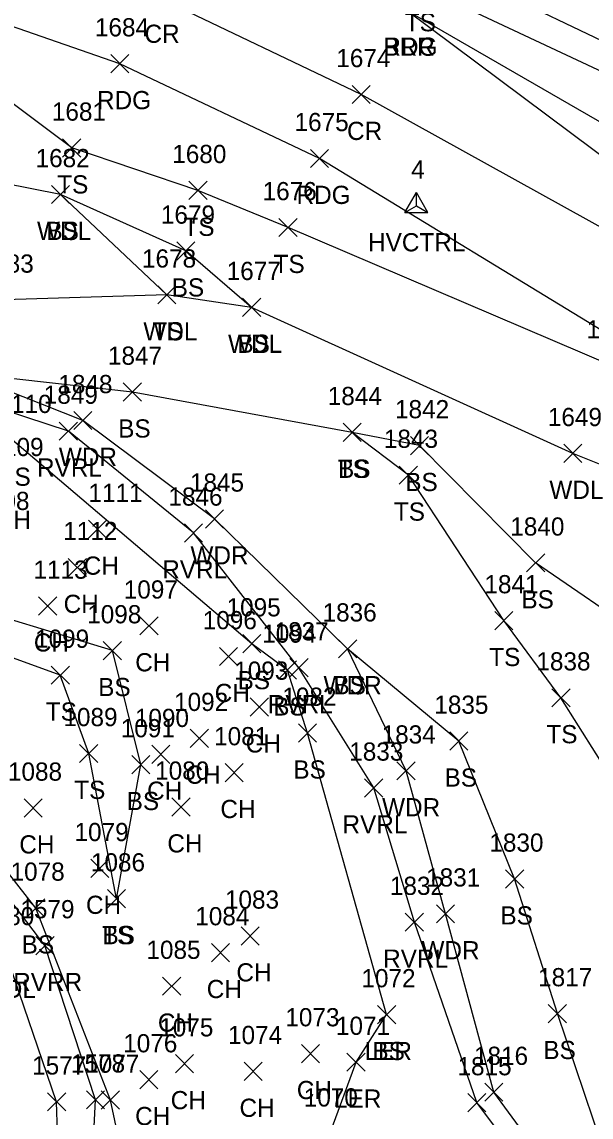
# Model space of a CAD drawing. Extents: x 1600281 to 1602254, y 862855 to 863227.
# Drawn here: x 1602106.5 to 1602169.1, y 862981.5 to 863101.9 of the extents above; entities that cross this region are included whole.
import ezdxf

# ---------------------------------------------------------------- set-up
doc = ezdxf.new("R2010")
doc.units = 0
for name, color, linetype in [('C_A', 7, 'Continuous'), ('C_I', 7, 'Continuous'), ('CPSM', 7, 'Continuous'), ('L_A', 7, 'Continuous'), ('L_I', 7, 'Continuous'), ('L_TIC', 7, 'Continuous'), ('LABL', 7, 'Continuous'), ('LARO', 7, 'Continuous'), ('LAWA', 7, 'Continuous'), ('LAWE', 7, 'Continuous'), ('LELB', 7, 'Continuous'), ('P_A', 7, 'Continuous'), ('P_I', 7, 'Continuous'), ('P_TIC', 7, 'Continuous'), ('PEU', 7, 'Continuous'), ('PRC', 7, 'Continuous')]:
    doc.layers.add(name, color=color, linetype=linetype)

msp = doc.modelspace()

# ---------------------------------------------------------------- linework, layer by layer
at = {"layer": 'CPSM'}
for p, q in [((1602148.62, 863080.92), (1602149.87, 863083.09)), ((1602151.12, 863080.92), (1602149.87, 863083.09)), ((1602149.87, 863081.64), (1602149.87, 863083.09)), ((1602148.62, 863080.92), (1602149.87, 863081.64)), ((1602149.87, 863081.64), (1602149.87, 863081.64)), ((1602149.87, 863081.64), (1602151.12, 863080.92)), ((1602148.62, 863080.92), (1602151.12, 863080.92))]:
    msp.add_line(p, q, dxfattribs=at)
at = {"layer": 'L_TIC'}
for points in [[(1602110.99, 863087), (1602112.99, 863089)], [(1602112.99, 863087), (1602110.99, 863089)], [(1602124.86, 863082.34), (1602126.86, 863084.34)], [(1602126.86, 863082.34), (1602124.86, 863084.34)], [(1602109.76, 863081.89), (1602111.76, 863083.89)], [(1602111.76, 863081.89), (1602109.76, 863083.89)], [(1602109.76, 863081.89), (1602111.76, 863083.89)], [(1602111.76, 863081.89), (1602109.76, 863083.89)], [(1602134.77, 863078.26), (1602136.77, 863080.26)], [(1602136.77, 863078.26), (1602134.77, 863080.26)], [(1602123.54, 863075.68), (1602125.54, 863077.68)], [(1602125.54, 863075.68), (1602123.54, 863077.68)], [(1602121.45, 863070.86), (1602123.45, 863072.86)], [(1602123.45, 863070.86), (1602121.45, 863072.86)], [(1602121.45, 863070.86), (1602123.45, 863072.86)], [(1602123.45, 863070.86), (1602121.45, 863072.86)], [(1602130.76, 863069.49), (1602132.76, 863071.49)], [(1602132.76, 863069.49), (1602130.76, 863071.49)], [(1602130.76, 863069.49), (1602132.76, 863071.49)], [(1602132.76, 863069.49), (1602130.76, 863071.49)], [(1602117.66, 863060.18), (1602119.66, 863062.18)], [(1602119.66, 863060.18), (1602117.66, 863062.18)], [(1602112.21, 863057.06), (1602114.21, 863059.06)], [(1602114.21, 863057.06), (1602112.21, 863059.06)], [(1602110.62, 863055.89), (1602112.62, 863057.89)], [(1602112.62, 863055.89), (1602110.62, 863057.89)], [(1602141.82, 863055.75), (1602143.82, 863057.75)], [(1602143.82, 863055.75), (1602141.82, 863057.75)], [(1602141.82, 863055.75), (1602143.82, 863057.75)], [(1602143.82, 863055.75), (1602141.82, 863057.75)], [(1602149.21, 863054.3), (1602151.21, 863056.3)], [(1602151.21, 863054.3), (1602149.21, 863056.3)], [(1602166.07, 863053.44), (1602168.07, 863055.44)], [(1602168.07, 863053.44), (1602166.07, 863055.44)], [(1602147.99, 863051.05), (1602149.99, 863053.05)], [(1602149.99, 863051.05), (1602147.99, 863053.05)], [(1602126.68, 863046.24), (1602128.68, 863048.24)], [(1602128.68, 863046.24), (1602126.68, 863048.24)], [(1602113.82, 863045.11), (1602115.82, 863047.11)], [(1602115.82, 863045.11), (1602113.82, 863047.11)], [(1602124.37, 863044.7), (1602126.37, 863046.7)], [(1602126.37, 863044.7), (1602124.37, 863046.7)], [(1602161.97, 863041.41), (1602163.97, 863043.41)], [(1602163.97, 863041.41), (1602161.97, 863043.41)], [(1602111.61, 863040.91), (1602113.61, 863042.91)], [(1602113.61, 863040.91), (1602111.61, 863042.91)], [(1602108.35, 863036.67), (1602110.35, 863038.67)], [(1602110.35, 863036.67), (1602108.35, 863038.67)], [(1602119.48, 863034.49), (1602121.48, 863036.49)], [(1602121.48, 863034.49), (1602119.48, 863036.49)], [(1602158.48, 863035.07), (1602160.48, 863037.07)], [(1602160.48, 863035.07), (1602158.48, 863037.07)], [(1602115.46, 863031.77), (1602117.46, 863033.77)], [(1602117.46, 863031.77), (1602115.46, 863033.77)], [(1602130.78, 863032.53), (1602132.78, 863034.53)], [(1602132.78, 863032.53), (1602130.78, 863034.53)], [(1602141.31, 863031.97), (1602143.31, 863033.97)], [(1602143.31, 863031.97), (1602141.31, 863033.97)], [(1602141.31, 863031.97), (1602143.31, 863033.97)], [(1602143.31, 863031.97), (1602141.31, 863033.97)], [(1602128.22, 863031.12), (1602130.22, 863033.12)], [(1602130.22, 863031.12), (1602128.22, 863033.12)], [(1602109.73, 863029.08), (1602111.73, 863031.08)], [(1602111.73, 863029.08), (1602109.73, 863031.08)], [(1602134.7, 863029.64), (1602136.7, 863031.64)], [(1602136.7, 863029.64), (1602134.7, 863031.64)], [(1602135.97, 863029.89), (1602137.97, 863031.89)], [(1602137.97, 863029.89), (1602135.97, 863031.89)], [(1602131.62, 863025.57), (1602133.62, 863027.57)], [(1602133.62, 863025.57), (1602131.62, 863027.57)], [(1602164.76, 863026.59), (1602166.76, 863028.59)], [(1602166.76, 863026.59), (1602164.76, 863028.59)], [(1602125.01, 863022.14), (1602127.01, 863024.14)], [(1602127.01, 863022.14), (1602125.01, 863024.14)], [(1602136.91, 863022.71), (1602138.91, 863024.71)], [(1602138.91, 863022.71), (1602136.91, 863024.71)], [(1602153.53, 863021.83), (1602155.53, 863023.83)], [(1602155.53, 863021.83), (1602153.53, 863023.83)], [(1602112.86, 863020.47), (1602114.86, 863022.47)], [(1602114.86, 863020.47), (1602112.86, 863022.47)], [(1602120.79, 863020.38), (1602122.79, 863022.38)], [(1602122.79, 863020.38), (1602120.79, 863022.38)], [(1602118.59, 863019.25), (1602120.59, 863021.25)], [(1602120.59, 863019.25), (1602118.59, 863021.25)], [(1602128.84, 863018.37), (1602130.84, 863020.37)], [(1602130.84, 863018.37), (1602128.84, 863020.37)], [(1602147.74, 863018.56), (1602149.74, 863020.56)], [(1602149.74, 863018.56), (1602147.74, 863020.56)], [(1602144.18, 863016.68), (1602146.18, 863018.68)], [(1602146.18, 863016.68), (1602144.18, 863018.68)], [(1602106.75, 863014.48), (1602108.75, 863016.48)], [(1602108.75, 863014.48), (1602106.75, 863016.48)], [(1602123.01, 863014.59), (1602125.01, 863016.59)], [(1602125.01, 863014.59), (1602123.01, 863016.59)], [(1602114.08, 863007.84), (1602116.08, 863009.84)], [(1602116.08, 863007.84), (1602114.08, 863009.84)], [(1602159.67, 863006.68), (1602161.67, 863008.68)], [(1602161.67, 863006.68), (1602159.67, 863008.68)], [(1602115.92, 863004.51), (1602117.92, 863006.51)], [(1602117.92, 863004.51), (1602115.92, 863006.51)], [(1602115.92, 863004.51), (1602117.92, 863006.51)], [(1602117.92, 863004.51), (1602115.92, 863006.51)], [(1602107.04, 863003.49), (1602109.04, 863005.49)], [(1602109.04, 863003.49), (1602107.04, 863005.49)], [(1602152.07, 863002.85), (1602154.07, 863004.85)], [(1602154.07, 863002.85), (1602152.07, 863004.85)], [(1602148.65, 863001.93), (1602150.65, 863003.93)], [(1602150.65, 863001.93), (1602148.65, 863003.93)], [(1602130.6, 863000.42), (1602132.6, 863002.42)], [(1602132.6, 863000.42), (1602130.6, 863002.42)], [(1602108.05, 862999.36), (1602110.05, 863001.36)], [(1602110.05, 862999.36), (1602108.05, 863001.36)], [(1602127.34, 862998.59), (1602129.34, 863000.59)], [(1602129.34, 862998.59), (1602127.34, 863000.59)], [(1602121.97, 862994.9), (1602123.97, 862996.9)], [(1602123.97, 862994.9), (1602121.97, 862996.9)], [(1602145.6, 862991.78), (1602147.6, 862993.78)], [(1602147.6, 862991.78), (1602145.6, 862993.78)], [(1602145.6, 862991.78), (1602147.6, 862993.78)], [(1602147.6, 862991.78), (1602145.6, 862993.78)], [(1602164.37, 862991.89), (1602166.37, 862993.89)], [(1602166.37, 862991.89), (1602164.37, 862993.89)], [(1602137.24, 862987.49), (1602139.24, 862989.49)], [(1602139.24, 862987.49), (1602137.24, 862989.49)], [(1602123.38, 862986.38), (1602125.38, 862988.38)], [(1602125.38, 862986.38), (1602123.38, 862988.38)], [(1602142.24, 862986.55), (1602144.24, 862988.55)], [(1602144.24, 862986.55), (1602142.24, 862988.55)], [(1602119.47, 862984.63), (1602121.47, 862986.63)], [(1602121.47, 862984.63), (1602119.47, 862986.63)], [(1602130.94, 862985.54), (1602132.94, 862987.54)], [(1602132.94, 862985.54), (1602130.94, 862987.54)], [(1602109.33, 862982.19), (1602111.33, 862984.19)], [(1602111.33, 862982.19), (1602109.33, 862984.19)], [(1602113.6, 862982.41), (1602115.6, 862984.41)], [(1602115.6, 862982.41), (1602113.6, 862984.41)], [(1602115.24, 862982.39), (1602117.24, 862984.39)], [(1602117.24, 862982.39), (1602115.24, 862984.39)], [(1602157.38, 862983.25), (1602159.38, 862985.25)], [(1602159.38, 862983.25), (1602157.38, 862985.25)], [(1602155.51, 862982.11), (1602157.51, 862984.11)], [(1602157.51, 862982.11), (1602155.51, 862984.11)]]:
    msp.add_lwpolyline(points, dxfattribs=at)
at = {"layer": 'LABL'}
msp.add_lwpolyline([(1602238.45, 863059.38), (1602199.34, 863071.62), (1602179.65, 863080.08), (1602148.76, 863103.13), (1602128.22, 863117.32), (1602101.61, 863126.76), (1602102.3, 863128.31), (1602102.99, 863130.69), (1602105.29, 863133.38), (1602108.93, 863139.2)], dxfattribs=at)
at = {"layer": 'LARO'}
msp.add_lwpolyline([(1602166.36, 862965.56), (1602156.39, 862968.63), (1602148.17, 862969.06), (1602143.59, 862971.28), (1602140.35, 862979.68), (1602143.24, 862987.55), (1602146.6, 862992.78)], dxfattribs=at)
at = {"layer": 'LAWA'}
for points in [[(1602234.91, 863039.66), (1602192.35, 863044.31), (1602167.07, 863054.44), (1602131.76, 863070.49), (1602122.45, 863071.86), (1602110.76, 863082.89), (1602097.95, 863085.4), (1602096.24, 863076.79), (1602085.95, 863068.22)], [(1602181.59, 862874.7), (1602187.9, 862909.63), (1602181.84, 862933.12), (1602183.65, 862946.17), (1602178.29, 862959.03), (1602166.54, 862973.13), (1602158.38, 862984.25), (1602153.07, 863003.85), (1602148.74, 863019.56), (1602142.31, 863032.97), (1602127.68, 863047.24), (1602113.21, 863058.06), (1602100.07, 863063.24), (1602085.95, 863068.22)], [(1602096.41, 862879.64), (1602095.37, 862902.03), (1602099.33, 862919.26), (1602109.63, 862945.96), (1602110.97, 862962.96), (1602110.33, 862983.19), (1602104.7, 862999.6), (1602098.83, 863009.48), (1602089.05, 863018.84), (1602087.06, 863019.48), (1602084.93, 863020.57), (1602083.85, 863020.87), (1602075.62, 863029.36), (1602062.85, 863014.97)]]:
    msp.add_lwpolyline(points, dxfattribs=at)
at = {"layer": 'LAWE'}
for points in [[(1602180.63, 862874.48), (1602183.92, 862910.83), (1602179.73, 862932.7), (1602183.06, 862946.01), (1602176.69, 862958.52), (1602164.73, 862972.16), (1602156.51, 862983.11), (1602149.65, 863002.93), (1602145.18, 863017.68), (1602136.97, 863030.89), (1602125.37, 863045.7), (1602111.62, 863056.89), (1602099.97, 863060.68), (1602084.89, 863067.15), (1602071.85, 863075.33)], [(1602098.44, 862879.18), (1602097.38, 862900.93), (1602100.82, 862918.12), (1602111.9, 862945.19), (1602113.66, 862964.28), (1602114.6, 862983.41), (1602109.05, 863000.36), (1602100.6, 863011.38), (1602088.42, 863022.64), (1602086.17, 863023.52), (1602076.98, 863030.19), (1602067.14, 863035), (1602054.87, 863040.58)]]:
    msp.add_lwpolyline(points, dxfattribs=at)
at = {"layer": 'LELB'}
for points in [[(1602241.55, 863072.3), (1602203.83, 863084.04), (1602184.9, 863092.77), (1602150.82, 863109.07), (1602129.54, 863119.04), (1602102.3, 863128.31), (1602095.85, 863125.02), (1602082.9, 863122.06), (1602071.56, 863117.44), (1602069.71, 863115.85), (1602064.38, 863110.75), (1602060.62, 863098.3)], [(1602240.62, 863068.77), (1602202.94, 863080.55), (1602183.74, 863090.05), (1602150.19, 863105.82), (1602128.22, 863117.32)], [(1602234.44, 863044.27), (1602194.2, 863054.35), (1602171.4, 863064.07), (1602135.77, 863079.26), (1602125.86, 863083.34), (1602111.99, 863088), (1602098.79, 863097.89), (1602087.9, 863090.25), (1602076.95, 863086.28)], [(1602131.76, 863070.49), (1602124.54, 863076.68), (1602110.76, 863082.89)], [(1602122.45, 863071.86), (1602104.61, 863071.3), (1602096.24, 863076.79), (1602089.53, 863080.77), (1602081.26, 863078.74), (1602074.76, 863082.54)], [(1602146.6, 862992.78), (1602137.91, 863023.71), (1602135.7, 863030.64), (1602131.78, 863033.53), (1602105.48, 863055.88), (1602088.59, 863055.94), (1602085.92, 863063.75), (1602070.59, 863074.73)], [(1602231.78, 862943.94), (1602226.26, 862961.53), (1602218.49, 862967.02), (1602194.13, 862990.83), (1602188.47, 863004.89), (1602184.54, 863016.14), (1602188.04, 863030.7), (1602174.95, 863034.2), (1602162.97, 863042.41), (1602150.21, 863055.3), (1602142.82, 863056.75), (1602118.66, 863061.18), (1602100.07, 863063.24)], [(1602197.44, 862931.78), (1602196.12, 862947.95), (1602189.93, 862968.99), (1602182.41, 862984.02), (1602177.66, 862997.92), (1602171.58, 863018.35), (1602165.76, 863027.59), (1602159.48, 863036.07), (1602148.99, 863052.05), (1602142.82, 863056.75)], [(1602099.84, 862878.35), (1602100.95, 862904.78), (1602110.59, 862929.64), (1602115.65, 862954.7), (1602118.28, 862973.93), (1602116.24, 862983.39), (1602108.04, 863004.49), (1602102.91, 863010.99), (1602095.9, 863019.12), (1602089.35, 863024.5), (1602085.54, 863025.45), (1602074.55, 863034.5), (1602069.63, 863039.23), (1602052.34, 863044.6)], [(1602116.92, 863005.51), (1602119.59, 863020.25), (1602116.46, 863032.77), (1602097.87, 863038.44), (1602093.06, 863039.18), (1602081.88, 863041.2), (1602069.63, 863039.23)], [(1602116.92, 863005.51), (1602113.86, 863021.47), (1602110.73, 863030.08), (1602095.7, 863035.54), (1602082.39, 863035.53), (1602074.55, 863034.5)], [(1602197.44, 862931.78), (1602192.57, 862946.47), (1602183.09, 862964.15), (1602171.3, 862975.32), (1602165.37, 862992.89), (1602160.67, 863007.68), (1602154.53, 863022.83), (1602142.31, 863032.97)]]:
    msp.add_lwpolyline(points, dxfattribs=at)
at = {"layer": 'P_TIC'}
for points in [[(1602116.28, 863096.26), (1602118.28, 863098.26)], [(1602118.28, 863096.26), (1602116.28, 863098.26)], [(1602142.81, 863092.88), (1602144.81, 863094.88)], [(1602144.81, 863092.88), (1602142.81, 863094.88)], [(1602138.22, 863085.85), (1602140.22, 863087.85)], [(1602140.22, 863085.85), (1602138.22, 863087.85)]]:
    msp.add_lwpolyline(points, dxfattribs=at)
at = {"layer": 'PEU'}
for points in [[(1602239.32, 863063.19), (1602201.86, 863077.58), (1602181.73, 863084.14), (1602148.76, 863103.13), (1602126.1, 863112.3), (1602096.31, 863123.24), (1602085.65, 863117.24), (1602075.42, 863112.31), (1602066.28, 863103.64), (1602062.25, 863097.25), (1602069.56, 863092.76), (1602076.19, 863089.04)], [(1602235.31, 863048.09), (1602195.24, 863059.48), (1602172.51, 863066.54), (1602139.22, 863086.85), (1602117.28, 863097.26), (1602100.05, 863103.22), (1602086.41, 863097.2), (1602076.19, 863089.04)]]:
    msp.add_lwpolyline(points, dxfattribs=at)
at = {"layer": 'PRC'}
msp.add_lwpolyline([(1602236.4, 863054.64), (1602198.66, 863067.23), (1602177.31, 863075.3), (1602143.81, 863093.88), (1602121.55, 863104.55), (1602098.78, 863113.5), (1602079.15, 863104.73), (1602069.56, 863092.76)], dxfattribs=at)

# ---------------------------------------------------------------- texts
at = {"layer": 'C_A'}
msp.add_text('HVCTRL', height=2, dxfattribs=at).set_placement((1602144.56, 863076.64))
at = {"layer": 'C_I'}
msp.add_text('4', height=2, dxfattribs=at).set_placement((1602149.3, 863084.64))
at = {"layer": 'L_A'}
for s, p in [('TS', (1602148.6, 863100.82)), ('BRR', (1602146.24, 863098.13)), ('TS', (1602110.4, 863083)), ('WDL', (1602108.18, 863077.89)), ('BS', (1602109.21, 863077.89)), ('TS', (1602124.27, 863078.34)), ('TS', (1602134.18, 863074.26)), ('BS', (1602122.98, 863071.68)), ('WDL', (1602119.86, 863066.86)), ('TS', (1602120.85, 863066.86)), ('WDL', (1602129.17, 863065.49)), ('BS', (1602130.2, 863065.49)), ('BS', (1602117.1, 863056.18)), ('WDR', (1602110.58, 863053.06)), ('BS', (1602103.92, 863050.88)), ('RVRL', (1602108.18, 863051.89)), ('TS', (1602141.23, 863051.75)), ('BS', (1602141.26, 863051.75)), ('BS', (1602148.65, 863050.3)), ('WDL', (1602164.49, 863049.44)), ('CH', (1602103.65, 863046.15)), ('TS', (1602147.4, 863047.05)), ('CH', (1602113.31, 863041.11)), ('WDR', (1602125.04, 863042.24)), ('RVRL', (1602121.94, 863040.7)), ('CH', (1602111.1, 863036.91)), ('BS', (1602161.41, 863037.41)), ('CH', (1602107.83, 863032.67)), ('CH', (1602118.97, 863030.49)), ('TS', (1602157.88, 863031.07)), ('BS', (1602130.22, 863028.53)), ('WDR', (1602139.67, 863027.97)), ('BS', (1602140.75, 863027.97)), ('BS', (1602114.9, 863027.77)), ('CH', (1602127.71, 863027.12)), ('RVRL', (1602133.54, 863025.89)), ('BS', (1602134.14, 863025.64)), ('TS', (1602109.14, 863025.08)), ('TS', (1602164.16, 863022.59)), ('CH', (1602131.11, 863021.57)), ('BS', (1602136.35, 863018.71)), ('CH', (1602124.5, 863018.14)), ('BS', (1602152.97, 863017.83)), ('TS', (1602112.27, 863016.47)), ('CH', (1602120.27, 863016.38)), ('BS', (1602118.03, 863015.25)), ('CH', (1602128.33, 863014.37)), ('WDR', (1602146.1, 863014.56)), ('RVRL', (1602141.75, 863012.68)), ('CH', (1602106.23, 863010.48)), ('CH', (1602122.5, 863010.59)), ('CH', (1602113.56, 863003.84)), ('BS', (1602159.11, 863002.68)), ('TS', (1602115.33, 863000.51)), ('BS', (1602115.37, 863000.51)), ('BS', (1602106.48, 862999.49)), ('RVRL', (1602146.22, 862997.93)), ('WDR', (1602150.43, 862998.85)), ('RVRR', (1602105.56, 862995.36)), ('CH', (1602130.09, 862996.42)), ('WDL', (1602102.11, 862994.6)), ('CH', (1602126.83, 862994.59)), ('CH', (1602121.46, 862990.9)), ('LER', (1602144.18, 862987.78)), ('BS', (1602145.04, 862987.78)), ('BS', (1602163.82, 862987.89)), ('CH', (1602136.73, 862983.49)), ('CH', (1602122.87, 862982.38)), ('LER', (1602140.82, 862982.55)), ('CH', (1602130.43, 862981.54)), ('CH', (1602118.96, 862980.63))]:
    msp.add_text(s, height=2, dxfattribs=at).set_placement(p)
at = {"layer": 'L_I'}
for s, p in [('1681', (1602109.81, 863091)), ('1682', (1602108.02, 863085.89)), ('1682', (1602108.02, 863085.89)), ('1680', (1602123.04, 863086.34)), ('1676', (1602132.97, 863082.26)), ('1679', (1602121.79, 863079.68)), ('1678', (1602119.71, 863074.86)), ('1678', (1602119.71, 863074.86)), ('1683', (1602101.87, 863074.3)), ('1677', (1602129.02, 863073.49)), ('1677', (1602129.02, 863073.49)), ('1650', (1602168.57, 863067.07)), ('1847', (1602115.97, 863064.18)), ('1848', (1602110.52, 863061.06)), ('1849', (1602108.92, 863059.89)), ('1844', (1602140.13, 863059.75)), ('1844', (1602140.13, 863059.75)), ('1110', (1602103.83, 863058.88)), ('1842', (1602147.52, 863058.3)), ('1649', (1602164.32, 863057.44)), ('1843', (1602146.3, 863055.05)), ('1109', (1602102.95, 863054.15)), ('1845', (1602124.98, 863050.24)), ('1111', (1602113.83, 863049.11)), ('1846', (1602122.62, 863048.7)), ('1108', (1602101.4, 863048.22)), ('1112', (1602111.06, 863044.91)), ('1840', (1602160.19, 863045.41)), ('1113', (1602107.79, 863040.67)), ('1841', (1602157.35, 863039.07)), ('1097', (1602117.71, 863038.49)), ('1095', (1602129.01, 863036.53)), ('1098', (1602113.69, 863035.77)), ('1096', (1602126.39, 863035.12)), ('1836', (1602139.56, 863035.97)), ('1836', (1602139.56, 863035.97)), ('1837', (1602134.28, 863033.89)), ('1099', (1602107.96, 863033.08)), ('1094', (1602132.93, 863033.64)), ('1838', (1602163.06, 863030.59)), ('1093', (1602129.85, 863029.57)), ('1082', (1602135.14, 863026.71)), ('1092', (1602123.24, 863026.14)), ('1835', (1602151.84, 863025.83)), ('1089', (1602111.08, 863024.47)), ('1090', (1602118.93, 863024.38)), ('1091', (1602117.38, 863023.25)), ('1081', (1602127.64, 863022.37)), ('1834', (1602146.05, 863022.56)), ('1833', (1602142.49, 863020.68)), ('1088', (1602104.98, 863018.48)), ('1080', (1602121.16, 863018.59)), ('1079', (1602112.3, 863011.84)), ('1830', (1602157.89, 863010.68)), ('1078', (1602105.27, 863007.49)), ('1086', (1602114.1, 863008.51)), ('1086', (1602114.1, 863008.51)), ('1831', (1602150.94, 863006.85)), ('1832', (1602146.96, 863005.93)), ('1083', (1602128.83, 863004.42)), ('1580', (1602101.92, 863002.6)), ('1579', (1602106.35, 863003.36)), ('1084', (1602125.57, 863002.59)), ('1085', (1602120.2, 862998.9)), ('1072', (1602143.83, 862995.78)), ('1072', (1602143.83, 862995.78)), ('1817', (1602163.25, 862995.89)), ('1073', (1602135.47, 862991.49)), ('1071', (1602141.03, 862990.55)), ('1075', (1602121.61, 862990.38)), ('1074', (1602129.17, 862989.54)), ('1076', (1602117.65, 862988.63)), ('1816', (1602156.2, 862987.25)), ('1577', (1602107.64, 862986.19)), ('1578', (1602111.91, 862986.41)), ('1077', (1602113.47, 862986.39)), ('1815', (1602154.39, 862986.11)), ('1070', (1602137.49, 862982.68))]:
    msp.add_text(s, height=2, dxfattribs=at).set_placement(p)
at = {"layer": 'P_A'}
for s, p in [('CR', (1602119.99, 863099.55)), ('RDG', (1602146.24, 863098.13)), ('RDG', (1602114.77, 863092.26)), ('CR', (1602142.25, 863088.88)), ('RDG', (1602136.7, 863081.85))]:
    msp.add_text(s, height=2, dxfattribs=at).set_placement(p)
at = {"layer": 'P_I'}
for s, p in [('1684', (1602114.54, 863100.26)), ('1674', (1602141.07, 863096.88)), ('1675', (1602136.48, 863089.85))]:
    msp.add_text(s, height=2, dxfattribs=at).set_placement(p)

doc.saveas('drawing.dxf')
